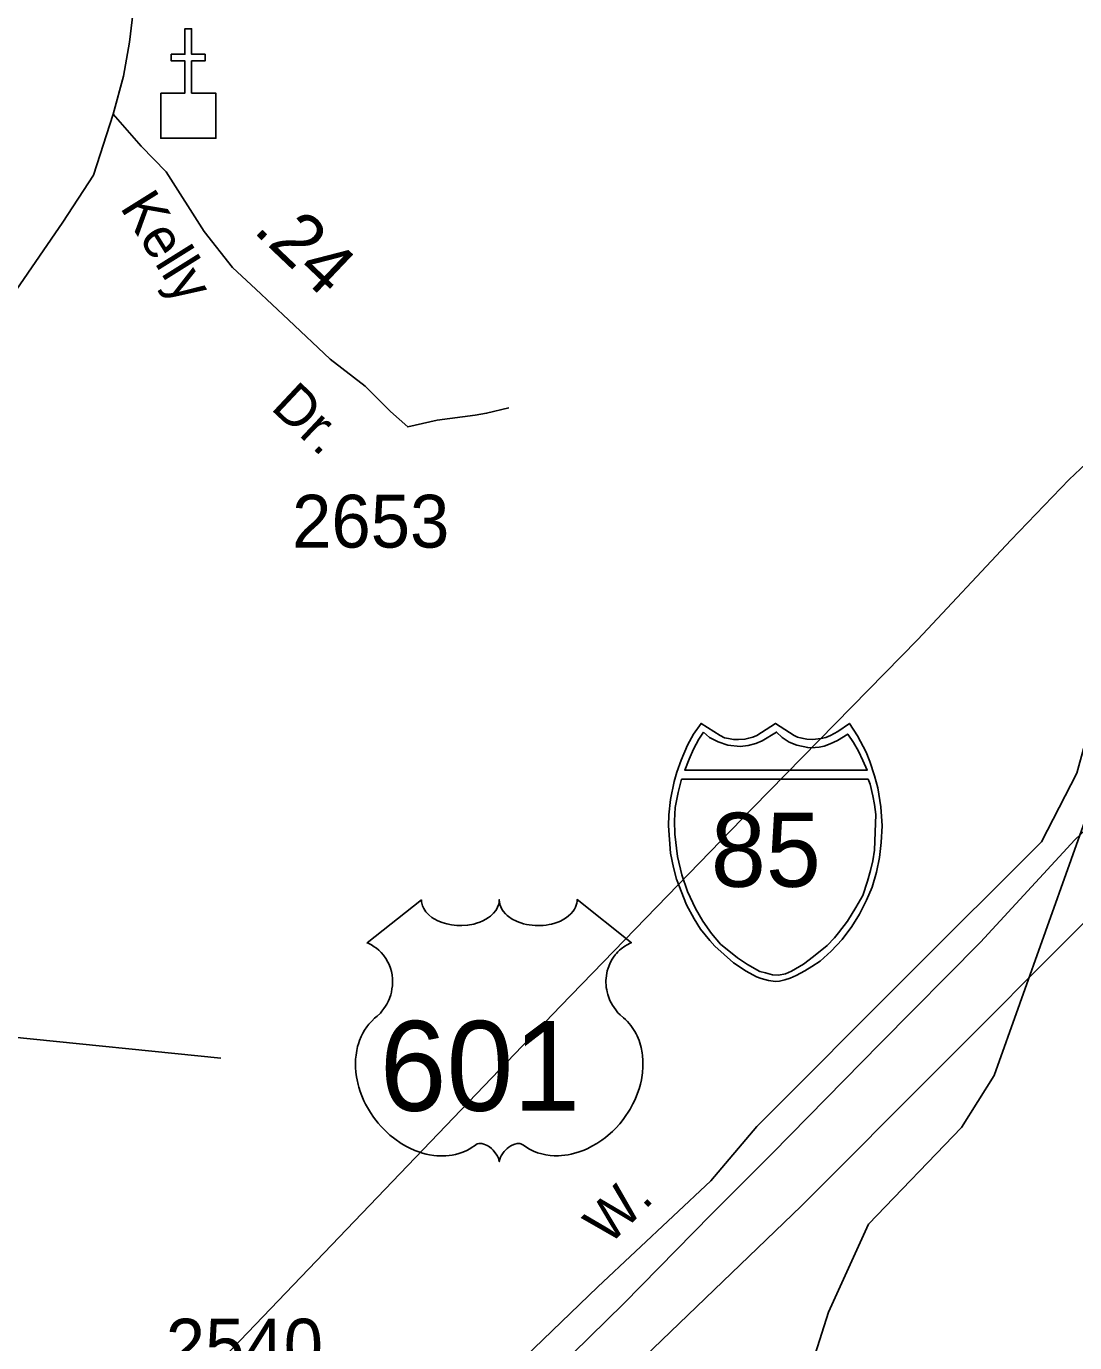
# Model space of a CAD drawing. Extents: x 1473865 to 1648260, y 639067 to 773536.
# Drawn here: x 1553331 to 1555810, y 686657 to 689770 of the extents above; entities that cross this region are included whole.
import ezdxf

# ---------------------------------------------------------------- set-up
doc = ezdxf.new("R2010")
doc.units = 0
for name, color, linetype in [('Exist Cultural Church CELL', 7, 'Continuous'), ('Exist Hydrographic Creek Single Shore', 7, 'Continuous'), ('Exist Road Non-System Type 51', 7, 'Continuous'), ('Exist Road Primary Interstate Divided Center Attributed', 7, 'Continuous'), ('Exist Road Primary Interstate Shield CELL', 7, 'Continuous'), ('Exist Road Primary Interstate Shield Number Label', 7, 'Continuous'), ('Exist Road Primary US Shield CELL', 7, 'Continuous'), ('Exist Road Primary US Shield Number Label', 7, 'Continuous'), ('Exist Road Secondary Mileage Hundredths English Label', 7, 'Continuous'), ('Exist Road Secondary Type 51 Attributed', 7, 'Continuous'), ('Exist Road Secondary Type 51 Label', 7, 'Continuous'), ('Exist Road Secondary Type 51 Number Label', 7, 'Continuous'), ('Exist Utilities Electrical Transmission Line', 7, 'Continuous')]:
    doc.layers.add(name, color=color, linetype=linetype)

msp = doc.modelspace()

# ---------------------------------------------------------------- linework, layer by layer
at = {"layer": 'Exist Cultural Church CELL'}
msp.add_lwpolyline([(1553648.8, 689612), (1553705.8, 689612.1), (1553705.8, 689688.3), (1553673.8, 689688.3), (1553673.8, 689704.2), (1553705.8, 689704.2), (1553705.8, 689764.4), (1553721.8, 689764.4), (1553721.8, 689704.2), (1553753.8, 689704.2), (1553753.8, 689688.3), (1553721.8, 689688.3), (1553721.8, 689612.1), (1553779.4, 689612), (1553779.4, 689505.6), (1553648.8, 689505.6)], close=True, dxfattribs=at)
at = {"layer": 'Exist Hydrographic Creek Single Shore'}
msp.add_lwpolyline([(1554925.6, 685765.8), (1554973.6, 685857.7), (1555102.6, 686157.1), (1555122.6, 686396.3), (1555227.7, 686729), (1555322.6, 686937.2), (1555542.6, 687165.8), (1555619.6, 687289), (1555862.6, 687970.1), (1556105.7, 688306.5), (1556233.7, 688848.9), (1556280.7, 689182.8), (1556332.7, 689332.7), (1556380.7, 689820.8), (1556433.7, 690013.3), (1556488.6, 690304.4), (1556539.7, 690385.4), (1556826.7, 690625.9), (1556887.7, 690831.3), (1557140.7, 691003.5), (1557217.7, 691175.9), (1557612.7, 691355), (1557662.7, 691386.9)], dxfattribs=at)
at = {"layer": 'Exist Road Non-System Type 51'}
msp.add_lwpolyline([(1552652.4, 687335.8), (1552734.4, 687327.4), (1552910.4, 687356.3), (1553006.9, 687370.8), (1553293.8, 687380.5), (1553790.5, 687329.8)], dxfattribs=at)
at = {"layer": 'Exist Road Primary Interstate Divided Center Attributed'}
for points in [[(1556033, 688056.7), (1555810.1, 687846.4), (1555587.3, 687604.2), (1555349.7, 687364), (1555094.6, 687104.5), (1554950.1, 686959.8), (1554743.6, 686749.6), (1553858.5, 685881.1), (1552788.7, 684799.4), (1552644.2, 684671.8)], [(1552610.6, 684465), (1552764, 684627.8), (1554092.3, 685949.2), (1555163.5, 686979.7), (1556160.2, 687979.4)]]:
    msp.add_lwpolyline(points, dxfattribs=at)
at = {"layer": 'Exist Road Primary Interstate Shield CELL'}
for points in [[(1555102.4, 687511.2), (1555111.9, 687512.1), (1555124.6, 687514.6), (1555137, 687518.6), (1555151.1, 687524.9), (1555172, 687536.4), (1555188.7, 687546.2), (1555208.1, 687559.2), (1555234.2, 687582.9), (1555260.2, 687610.4), (1555283.2, 687641.4), (1555301.5, 687670.4), (1555317.6, 687703.6), (1555331, 687734.5), (1555341.7, 687769.8), (1555348.7, 687804.1), (1555352.3, 687839.7), (1555354.7, 687879.3), (1555352, 687923.9), (1555344.2, 687969.4), (1555337, 687997.8), (1555325.9, 688031.7), (1555316.9, 688053.4), (1555296.1, 688091.8), (1555277.4, 688121.4), (1555250.1, 688102.3), (1555232.4, 688092.8), (1555221.5, 688087.9), (1555210.4, 688085.8), (1555189.9, 688083.3), (1555177, 688083.9), (1555165, 688086.6), (1555154.9, 688088.8), (1555146.7, 688092.8), (1555102.4, 688121.4), (1555058.2, 688092.8), (1555048.9, 688088.6), (1555039.4, 688086.6), (1555030.2, 688084), (1555015.1, 688083.3), (1555003.5, 688083.6), (1554991.6, 688085.8), (1554982.3, 688087.7), (1554971.8, 688092.8), (1554926.6, 688121.4), (1554908.9, 688095.7), (1554894.4, 688070.3), (1554879.1, 688034.4), (1554869.5, 688006.5), (1554862.7, 687983.7), (1554854.4, 687941.7), (1554850.1, 687905.2), (1554849.3, 687879.3), (1554854.1, 687814.8), (1554861.1, 687780.4), (1554868.3, 687752.7), (1554892.2, 687692.6), (1554910.1, 687659), (1554925.5, 687634.8), (1554947.1, 687607.7), (1554958.8, 687594.7), (1555003.6, 687555.5), (1555033.5, 687535.1), (1555057.4, 687522.2), (1555068.7, 687517.9), (1555086.3, 687513)], [(1554932, 688100.7), (1554921, 688083.8), (1554908.3, 688060.9), (1554898.2, 688037.2), (1554887.8, 688011.1), (1555319.4, 688010.9), (1555309.4, 688033.4), (1555298.6, 688055.9), (1555287.3, 688076.4), (1555273.6, 688096.3), (1555249.4, 688081.1), (1555231.8, 688072.8), (1555217.6, 688067.9), (1555205.6, 688065.2), (1555187, 688063.7), (1555178.7, 688064.2), (1555152.8, 688070.1), (1555135.2, 688077.2), (1555118.5, 688088.4), (1555105, 688101.1), (1555070.8, 688080.4), (1555055.7, 688073.7), (1555038.2, 688069.3), (1555019.1, 688066.9), (1554989.7, 688070.1), (1554966.6, 688078), (1554946.7, 688088.4)], [(1555321.9, 687989.6), (1555326.6, 687977.4), (1555332.9, 687950.4), (1555336.3, 687929.6), (1555339.7, 687905.6), (1555338.5, 687864.4), (1555336.5, 687821.9), (1555332.6, 687796.6), (1555327.4, 687773.7), (1555320.2, 687748.2), (1555308.7, 687714.4), (1555292.8, 687685.8), (1555272.9, 687653.9), (1555251.4, 687626.1), (1555242.1, 687614.5), (1555224.4, 687595.8), (1555192.2, 687570), (1555168.6, 687552.4), (1555140.5, 687535.8), (1555126.1, 687529.4), (1555109.5, 687525.9), (1555095.8, 687526.9), (1555079.1, 687531.3), (1555065.7, 687535), (1555036.3, 687550.9), (1555012.4, 687566.8), (1554972.6, 687599.4), (1554951.2, 687624.5), (1554931.1, 687653.9), (1554913.3, 687684), (1554894.2, 687723.7), (1554880.7, 687763.6), (1554871, 687806.7), (1554864.4, 687859.3), (1554863.6, 687891.4), (1554865.6, 687922.2), (1554868.5, 687938.4), (1554872.4, 687958.4), (1554880.3, 687989.4)]]:
    msp.add_lwpolyline(points, close=True, dxfattribs=at)
at = {"layer": 'Exist Road Primary US Shield CELL'}
msp.add_lwpolyline([(1554265.3, 687704.5), (1554265.7, 687699.2), (1554266.9, 687692.9), (1554267.9, 687689.6), (1554270.9, 687683.4), (1554275.8, 687676), (1554282.6, 687668.8), (1554290.2, 687662.5), (1554295.4, 687659.2), (1554304.2, 687654.4), (1554314.1, 687650.3), (1554325.2, 687647.1), (1554336.5, 687644.8), (1554348.9, 687643.4), (1554361.1, 687643.2), (1554374.3, 687644.2), (1554388.9, 687647), (1554395.7, 687648.8), (1554403.2, 687651.3), (1554410.2, 687654.2), (1554417.9, 687658.3), (1554424, 687662.3), (1554428.8, 687665.8), (1554435.7, 687672.3), (1554441.1, 687679.1), (1554443.4, 687682.9), (1554445.3, 687686.5), (1554448, 687694.3), (1554448.8, 687697.7), (1554449.3, 687704.8), (1554449.8, 687698.8), (1554450.4, 687695.1), (1554451.4, 687691.5), (1554452.9, 687687.6), (1554455.6, 687682.1), (1554458.7, 687677.5), (1554464.4, 687670.8), (1554468, 687667.4), (1554471.2, 687664.8), (1554480, 687658.8), (1554490.2, 687653.6), (1554495.2, 687651.4), (1554500.4, 687649.6), (1554506.9, 687647.6), (1554513.7, 687646), (1554520.3, 687644.9), (1554527.2, 687643.9), (1554534.2, 687643.4), (1554539.9, 687643.2), (1554546.9, 687643.3), (1554553.3, 687643.7), (1554559.9, 687644.4), (1554567.2, 687645.6), (1554573.1, 687646.9), (1554580.8, 687649), (1554587.8, 687651.5), (1554593.9, 687654.1), (1554601.9, 687658.3), (1554608.4, 687662.4), (1554613.1, 687666.2), (1554618.7, 687671.3), (1554624, 687677.5), (1554627.1, 687682), (1554629.3, 687686.6), (1554631.4, 687691.5), (1554632.6, 687696.6), (1554633.2, 687701.1), (1554633.4, 687704.9), (1554762, 687602.5), (1554758.9, 687601.3), (1554751.9, 687597.9), (1554746.4, 687594.6), (1554737.6, 687588.4), (1554733.8, 687585), (1554730, 687581.4), (1554726.5, 687577.6), (1554723.4, 687574.1), (1554719.7, 687568.9), (1554716.3, 687563.7), (1554713.1, 687558), (1554710.7, 687553.1), (1554706.7, 687542.7), (1554704.8, 687536.2), (1554703.6, 687530.7), (1554702.1, 687519.2), (1554701.7, 687513.7), (1554701.7, 687508.3), (1554702, 687502.6), (1554702.5, 687497.2), (1554703.5, 687491.5), (1554704.4, 687486.4), (1554706, 687480.3), (1554708.3, 687473.1), (1554711.1, 687466.2), (1554717, 687455.1), (1554724.6, 687443.7), (1554730, 687437.3), (1554735.3, 687431.8), (1554743.2, 687425.1), (1554747.5, 687421.3), (1554752.4, 687416.4), (1554760.5, 687407), (1554763.8, 687402.6), (1554767.1, 687397.7), (1554770.1, 687392.6), (1554773.1, 687387.1), (1554775.6, 687382.3), (1554780.1, 687371.3), (1554783.4, 687360.6), (1554784.9, 687355), (1554787.3, 687342.4), (1554788.2, 687336.1), (1554789.2, 687323.8), (1554789.2, 687308.9), (1554788.1, 687294.8), (1554785.4, 687278.3), (1554783.2, 687268.4), (1554779.9, 687257), (1554776.6, 687247), (1554770.7, 687232.3), (1554765.5, 687221.7), (1554758.7, 687209.2), (1554754.1, 687201.7), (1554748.7, 687193.7), (1554742, 687184.4), (1554734.1, 687174.5), (1554724.6, 687164.1), (1554716.9, 687156.4), (1554706.9, 687147.5), (1554700.8, 687142.4), (1554692.1, 687135.9), (1554680.3, 687128), (1554668.6, 687121.2), (1554658.6, 687116.2), (1554649.8, 687112.4), (1554638.4, 687108), (1554619.5, 687102.8), (1554612.5, 687101.3), (1554604.3, 687100.1), (1554596.7, 687099.4), (1554589.2, 687098.9), (1554579.2, 687098.9), (1554569.3, 687099.7), (1554559.8, 687101), (1554550, 687103.1), (1554539.8, 687106.1), (1554530.5, 687109.8), (1554521.1, 687114.4), (1554505.2, 687124.4), (1554500.6, 687126.9), (1554498, 687127.6), (1554491.8, 687127.9), (1554486.1, 687126.6), (1554480.1, 687124.3), (1554476.6, 687122.4), (1554471.8, 687119.3), (1554468.2, 687116.4), (1554463.8, 687112.2), (1554460.7, 687108.7), (1554458.4, 687106), (1554453.9, 687098.9), (1554452.3, 687095.6), (1554450.7, 687091.2), (1554449.2, 687084.9), (1554447.2, 687092.9), (1554444.8, 687098.2), (1554442.1, 687102.8), (1554439.2, 687106.8), (1554434.8, 687112), (1554430.7, 687115.9), (1554425.9, 687119.8), (1554420.7, 687122.9), (1554416.6, 687125), (1554412.8, 687126.5), (1554408.1, 687127.6), (1554404.3, 687127.9), (1554401.2, 687127.9), (1554396.9, 687126.9), (1554391.1, 687122.7), (1554385.6, 687118.9), (1554379.6, 687115.2), (1554372.5, 687111.4), (1554367.2, 687108.9), (1554361, 687106.5), (1554353.7, 687104.1), (1554345.8, 687102), (1554337.7, 687100.4), (1554330.6, 687099.3), (1554322.9, 687098.6), (1554316, 687098.4), (1554308.8, 687098.5), (1554302, 687099), (1554294.2, 687099.7), (1554284.5, 687101.1), (1554276.4, 687102.9), (1554267.9, 687105.2), (1554259.2, 687107.9), (1554249.8, 687111.5), (1554238.1, 687116.6), (1554230, 687120.8), (1554217.2, 687128.2), (1554202.1, 687138.6), (1554190.8, 687147.8), (1554182.5, 687155.3), (1554170.2, 687167.8), (1554163.1, 687175.9), (1554151.8, 687190.5), (1554144.6, 687201), (1554139.9, 687208.8), (1554133.1, 687221.2), (1554129.3, 687229.1), (1554124.4, 687240.5), (1554120.6, 687250.9), (1554117.4, 687260.8), (1554115.7, 687267.1), (1554113.3, 687278.1), (1554111.8, 687285.9), (1554110.3, 687296.6), (1554109.5, 687307.9), (1554109.4, 687318.4), (1554109.7, 687327), (1554110.7, 687337.1), (1554112.4, 687347.8), (1554114.4, 687357), (1554116.3, 687363.6), (1554119, 687371.7), (1554122.6, 687380.6), (1554126.9, 687389.1), (1554130.9, 687396.2), (1554136, 687403.8), (1554141, 687410.2), (1554147.6, 687417.4), (1554154.4, 687423.9), (1554160.7, 687429), (1554168.1, 687436.3), (1554172, 687440.7), (1554176.7, 687446.8), (1554180.4, 687452.5), (1554183.4, 687457.6), (1554187.3, 687465.2), (1554189.6, 687470.8), (1554192.6, 687479.4), (1554194.1, 687485.5), (1554195.6, 687493.4), (1554196.6, 687500.7), (1554197, 687509.9), (1554196.7, 687517.5), (1554195.8, 687526.4), (1554194.1, 687534.9), (1554192.1, 687542.4), (1554188.9, 687550.9), (1554186, 687557.1), (1554181, 687565.5), (1554175.6, 687573.4), (1554169.9, 687579.8), (1554164.2, 687585.4), (1554158.7, 687589.7), (1554153.5, 687593.4), (1554147, 687597.4), (1554140.7, 687600.5), (1554136.7, 687602.1)], close=True, dxfattribs=at)
at = {"layer": 'Exist Road Secondary Type 51 Attributed'}
for points in [[(1553507.4, 691129.5), (1553535.4, 691029.7), (1553579.5, 690857), (1553617.6, 690704.4), (1553610, 690562), (1553619.3, 690387.7), (1553603.2, 690162.7), (1553599.1, 689963.6), (1553587.2, 689839), (1553574.9, 689732.3), (1553560.6, 689652.3), (1553536, 689562)], [(1556298.2, 690848), (1556249.6, 690828), (1556186.8, 690741.5), (1556179, 690625.7), (1556171.6, 689742.3), (1556189.7, 689555.2), (1556165.6, 689354), (1556125.4, 689131.4), (1556021.2, 688798), (1555939.1, 688492.3), (1555871.1, 688207.9), (1555815.1, 688003.7), (1555731.9, 687841.5), (1555417.7, 687528.4), (1555058.4, 687167.7), (1554949.7, 687039.4), (1554682.8, 686789.2), (1554423, 686538.9), (1554026.4, 686170.4)], [(1553536, 689562), (1553489.9, 689418), (1553416.9, 689307.2), (1553250.9, 689065.5), (1553167.9, 688886.8), (1553070.6, 688699.1), (1553000.5, 688554.1), (1552869.4, 688322.2), (1552766.5, 688129.6), (1552695.2, 687964.4), (1552642.6, 687786.9), (1552633.9, 687662.1), (1552640.4, 687547.3), (1552652.5, 687421), (1552652.4, 687335.8), (1552675, 687151.9), (1552676.2, 687049.9), (1552738.7, 686557.8)], [(1553536, 689562), (1553602.4, 689486.4), (1553661.4, 689425.6), (1553751.3, 689285), (1553818.3, 689200.1), (1553874, 689148.8), (1553951, 689076.3), (1554049.6, 688982.6), (1554132.3, 688919), (1554191.8, 688859.5), (1554232.8, 688822.5), (1554302.5, 688839), (1554392.6, 688850.5), (1554419.2, 688854.9), (1554472.2, 688868.2)]]:
    msp.add_lwpolyline(points, dxfattribs=at)
at = {"layer": 'Exist Utilities Electrical Transmission Line'}
msp.add_lwpolyline([(1553655.7, 686473.7), (1554341.1, 687188.4), (1554594.1, 687452.4), (1555049.2, 687921.7), (1555439.3, 688320), (1555658.7, 688554.9), (1555796.9, 688698.7), (1555997.8, 688887.8), (1556316.5, 689191.1), (1556462.5, 689327), (1556630.8, 689486.5), (1556799.4, 689650), (1556961.9, 689807.5), (1557136.3, 689973.1), (1557349.5, 690183.9), (1557672.4, 690509.1), (1557995.4, 690838.6), (1558277.8, 691128.4), (1558671.7, 691520.7), (1558927.8, 691786.8)], dxfattribs=at)

# ---------------------------------------------------------------- texts
at = {"layer": 'Exist Road Primary Interstate Shield Number Label'}
msp.add_text('85', height=175, dxfattribs=at).set_placement((1554949.6, 687735))
at = {"layer": 'Exist Road Primary US Shield Number Label'}
msp.add_text('601', height=212.5, dxfattribs=at).set_placement((1554166.5, 687205.2))
at = {"layer": 'Exist Road Secondary Mileage Hundredths English Label'}
msp.add_text('.24', height=125, rotation=316.4658, dxfattribs=at).set_placement((1553864.6, 689285.5))
at = {"layer": 'Exist Road Secondary Type 51 Label'}
for s, rotation, p in [('Kelly', 302.0034, (1553550.9, 689342.2)), ('Dr.', 316.8369, (1553906.4, 688865.9)), ('W.', 45.0263, (1554708.4, 686884.5))]:
    msp.add_text(s, height=95, rotation=rotation, dxfattribs=at).set_placement(p)
at = {"layer": 'Exist Road Secondary Type 51 Number Label'}
for s, p in [('2653', (1553959.4, 688537.2)), ('2540', (1553660.7, 686588.4))]:
    msp.add_text(s, height=125, dxfattribs=at).set_placement(p)

doc.saveas('drawing.dxf')
